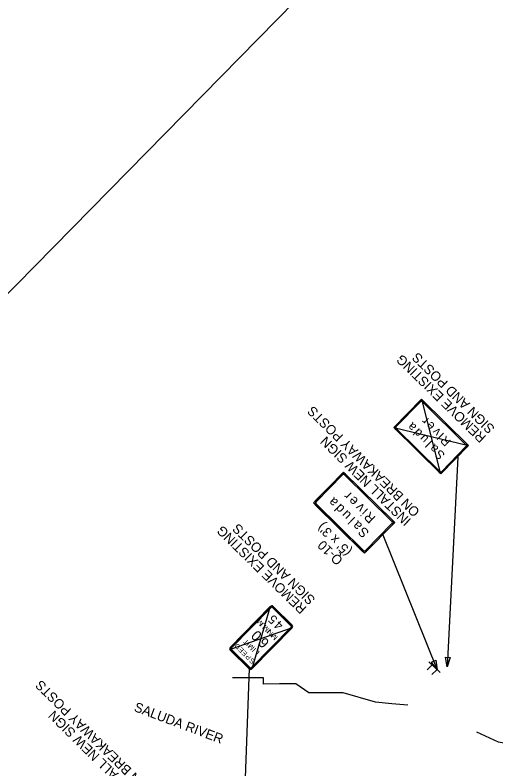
# Model space of a CAD drawing. Extents: x -5665 to 1997148, y 4 to 812485.
# Drawn here: x 1960138 to 1961396, y 797671 to 799640 of the extents above; entities that cross this region are included whole.
import ezdxf

# ---------------------------------------------------------------- set-up
doc = ezdxf.new("R2010")
doc.units = 0
for name, color, linetype in [('RD_EX_H20_TX', 7, 'Continuous'), ('RD_EX_Misc', 7, 'Continuous'), ('RD_PD_Final_TX', 7, 'Continuous'), ('RD_SHT_ID', 7, 'Continuous'), ('RD_SHT_TX', 7, 'Continuous')]:
    doc.layers.add(name, color=color, linetype=linetype)

msp = doc.modelspace()

# ---------------------------------------------------------------- linework, layer by layer
at = {"layer": 'RD_EX_H20_TX'}
msp.add_lwpolyline([(1962404, 800141.4), (1963753.3, 798814), (1964835.2, 797771.3), (1960364.2, 793199.8), (1958829.3, 794809.7), (1958381.6, 795250.1), (1957464.7, 796215.1), (1961650.1, 800469.8)], close=True, dxfattribs=at)
at = {"layer": 'RD_EX_Misc'}
for p, q in [((1961295.8, 798485.3), (1961268.2, 797937.9)), ((1960730.9, 797390.2), (1960751.5, 797933.4))]:
    msp.add_line(p, q, dxfattribs=at)
at = {"layer": 'RD_PD_Final_TX'}
for points in [[(1961226.9, 797950.3), (1961238.3, 797955.1), (1961242.2, 797929.8)], [(1961264.1, 797963.2), (1961276.5, 797962.2), (1961268.2, 797937.9)]]:
    msp.add_lwpolyline(points, close=True, dxfattribs=at)
at = {"layer": 'RD_SHT_ID'}
for points in [[(1961165.7, 797837.4), (1961123.4, 797841.3), (1961081.1, 797845.2), (1960996.3, 797869.9), (1960906.4, 797870.3), (1960872.3, 797893.3), (1960830, 797893), (1960787.7, 797892.6), (1960787.6, 797909.5), (1960735.8, 797909.1), (1960707.2, 797908.9)], [(1961345.1, 797768), (1961401.3, 797742), (1961401.3, 797742), (1961437.4, 797736), (1961492, 797726.8), (1961530.7, 797705)]]:
    msp.add_lwpolyline(points, dxfattribs=at)
at = {"layer": 'RD_SHT_TX'}
for p, q in [((1961201, 798636.6), (1961248.8, 798448.4)), ((1961128.5, 798562.8), (1961324, 798515.6)), ((1961099.8, 798282.4), (1961242.2, 797929.8)), ((1960805.8, 798095.6), (1960700.7, 797988.6)), ((1960805.8, 798095.6), (1960757.7, 797932.5)), ((1960862.8, 798046.5), (1960812.9, 798095.6)), ((1960862.9, 798039.5), (1960703.1, 797983.9)), ((1960757.7, 797932.5), (1960862.9, 798039.5)), ((1960700.7, 797981.6), (1960750.6, 797932.5)), ((1961249.6, 797922.7), (1961220, 797951.2)), ((1961216.2, 797930.1), (1961228.6, 797943)), ((1961228.4, 797917.4), (1961240.8, 797930.3))]:
    msp.add_line(p, q, dxfattribs=at)
for points in [[(1961324, 798515.6), (1961201, 798636.6), (1961128.5, 798562.8), (1961251.4, 798441.8), (1961324, 798515.6), (1961324, 798515.6), (1961324, 798515.6)], [(1961198.5, 798629.9), (1961135, 798565.4)], [(1961198.5, 798629.9), (1961198.5, 798629.9), (1961198.5, 798629.9)], [(1961317.4, 798518.1), (1961203.6, 798630)], [(1961135.1, 798560.3), (1961248.8, 798448.4)], [(1961135.1, 798560.3), (1961135.1, 798560.3), (1961135.1, 798560.3)], [(1961317.4, 798518.1), (1961317.4, 798518.1), (1961317.4, 798518.1)], [(1961253.9, 798448.4), (1961317.4, 798513)], [(1961131, 798314.8), (1960997.3, 798446.3), (1960918.4, 798366.1), (1961052.1, 798234.6), (1961131, 798314.8), (1961131, 798314.8), (1961131, 798314.8)], [(1960923.4, 798371.1), (1960992.4, 798441.3)], [(1960994.6, 798439.1), (1960925.6, 798368.9)], [(1960994.6, 798439.1), (1960994.6, 798439.1), (1960994.6, 798439.1)], [(1961123.8, 798317.5), (1961000.1, 798439.1)], [(1961002.3, 798441.3), (1961126, 798319.7)], [(1961253.9, 798448.4), (1961253.9, 798448.4), (1961253.9, 798448.4)], [(1961047.1, 798239.5), (1960923.4, 798361.1)], [(1960925.6, 798363.4), (1961049.3, 798241.7)], [(1960925.6, 798363.4), (1960925.6, 798363.4), (1960925.6, 798363.4)], [(1961054.8, 798241.8), (1961123.8, 798312)], [(1961126.1, 798309.8), (1961057, 798239.6)], [(1961123.8, 798317.5), (1961123.8, 798317.5), (1961123.8, 798317.5)], [(1961054.8, 798241.8), (1961054.8, 798241.8), (1961054.8, 798241.8)], [(1960806.7, 798094.7), (1960701.5, 797987.8)], [(1960703, 797986.3), (1960808.2, 798093.2)], [(1960806.7, 798094.7), (1960806.7, 798094.7), (1960806.7, 798094.7)], [(1960810.6, 798093.3), (1960860.5, 798044.2)], [(1960861.9, 798045.6), (1960812, 798094.7)], [(1960861.9, 798045.6), (1960861.9, 798045.6), (1960861.9, 798045.6)], [(1960860.5, 798041.8), (1960755.3, 797934.9)], [(1960756.8, 797933.4), (1960862, 798040.3)], [(1960701.6, 797982.5), (1960751.5, 797933.4)], [(1960701.6, 797982.5), (1960701.6, 797982.5), (1960701.6, 797982.5)], [(1960753, 797934.9), (1960703.1, 797983.9)], [(1960756.8, 797933.4), (1960756.8, 797933.4), (1960756.8, 797933.4)]]:
    msp.add_lwpolyline(points, dxfattribs=at)
for centre, radius, start, end in [((1961201.1, 798627.4), 6.47, 45.4705, 135.4707), ((1961201.1, 798627.4), 3.59, 45.4705, 135.4707), ((1961137.6, 798562.8), 6.47, 135.4705, 225.4707), ((1961137.6, 798562.8), 3.59, 135.4705, 225.4707), ((1961314.9, 798515.5), 3.59, 315.4703, 45.4705), ((1961314.9, 798515.5), 6.47, 315.4703, 45.4705), ((1960997.4, 798436.3), 7.03, 45.4705, 135.4707), ((1960997.4, 798436.3), 3.91, 45.4705, 135.4707), ((1961251.4, 798450.9), 6.47, 225.4707, 315.4703), ((1961251.4, 798450.9), 3.59, 225.4707, 315.4703), ((1960928.4, 798366.1), 7.03, 135.4705, 225.4707), ((1960928.4, 798366.1), 3.91, 135.4705, 225.4707), ((1961121.1, 798314.7), 3.91, 315.4703, 45.4705), ((1961121.1, 798314.7), 7.03, 315.4703, 45.4705), ((1961052, 798244.5), 3.91, 225.4707, 315.4703), ((1961052, 798244.5), 7.03, 225.4707, 315.4703), ((1960809.4, 798092.1), 5, 45.4705, 135.4707), ((1960809.4, 798092.1), 3.75, 45.4705, 135.4707), ((1960809.4, 798092.1), 1.67, 45.4705, 135.4707), ((1960859.3, 798043), 3.75, 315.4703, 45.4705), ((1960859.3, 798043), 5, 315.4703, 45.4705), ((1960859.3, 798043), 1.67, 315.4703, 45.4705), ((1960704.2, 797985.1), 5, 135.4705, 225.4707), ((1960704.2, 797985.1), 3.75, 135.4705, 225.4707), ((1960704.2, 797985.1), 1.67, 135.4705, 225.4707), ((1960754.1, 797936), 5, 225.4707, 315.4703), ((1960754.1, 797936), 3.75, 225.4707, 315.4703), ((1960754.1, 797936), 1.67, 225.4707, 315.4703)]:
    msp.add_arc(centre, radius, start, end, dxfattribs=at)

# ---------------------------------------------------------------- texts
for s, height, rotation, p in [('SIGN AND POSTS', 25, 135.6376, (1961394.5, 798562.2)), ('REMOVE EXISTING', 25, 135.6376, (1961371.7, 798539)), ('ON BREAKAWAY POSTS', 25, 135.4705, (1961198.4, 798344.8)), ('a', 23, 135.4705, (1961189.7, 798566)), ('r', 23, 135.4705, (1961222.1, 798584.6)), ('e', 23, 135.4705, (1961237.9, 798569)), ('d', 23, 135.4705, (1961205.4, 798550.6)), ('v', 23, 135.4705, (1961253.5, 798553.7)), ('INSTALL NEW SIGN', 25, 135.4705, (1961175.5, 798321.6)), ('u', 23, 135.4705, (1961221.1, 798535.2)), ('i', 23, 135.4705, (1961261.2, 798546.1)), ('R', 23, 135.4705, (1961279.8, 798527.8)), ('l', 23, 135.4705, (1961230.5, 798525.9)), ('a', 23, 135.4705, (1961247.3, 798509.3)), ('S', 23, 135.4705, (1961264.2, 798492.7)), ('a', 25, 135.4705, (1960985, 798369.6)), ('r', 25, 135.4705, (1961020.2, 798389.8)), ('e', 25, 135.4705, (1961037.4, 798372.9)), ('d', 25, 135.4705, (1961002.1, 798352.8)), ('v', 25, 135.4705, (1961054.4, 798356.2)), ('u', 25, 135.4705, (1961019.1, 798336)), ('i', 25, 135.4705, (1961062.7, 798347.9)), ('R', 25, 135.4705, (1961082.9, 798328.1)), ('l', 25, 135.4705, (1961029.4, 798326)), ('a', 25, 135.4705, (1961047.7, 798308)), ('REMOVE EXISTING', 25, 135.6376, (1960902.3, 798091.9)), ('SIGN AND POSTS', 25, 135.6376, (1960925, 798115.2)), ("(5' x 3')", 25, 135.6376, (1961020.3, 798241.6)), ('S', 25, 135.4705, (1961066, 798289.9)), ('Q-10', 25, 135.6376, (1960997.5, 798218.4)), ('5', 23.3, 135.4705, (1960826.4, 798063.6)), ('M', 13.3, 135.4705, (1960788.9, 798052.6)), ('U', 13.3, 135.4705, (1960796.1, 798045.5)), ('M', 13.3, 135.4705, (1960804.3, 798037.5)), ('4', 23.3, 135.4705, (1960841.8, 798048.5)), ('0', 26.7, 135.4705, (1960785.9, 798021.6)), ('I', 13.3, 135.4705, (1960807.6, 798034.2)), ('N', 13.3, 135.4705, (1960814.8, 798027.1)), ('I', 13.3, 135.4705, (1960818.2, 798023.8)), ('M', 13.3, 135.4705, (1960826.3, 798015.8)), ('T', 13.3, 135.4705, (1960750.9, 798003.5)), ('6', 26.7, 135.4705, (1960805, 798002.9)), ('D', 13.3, 135.4705, (1960729.1, 797991.1)), ('E', 13.3, 135.4705, (1960738.1, 797982.2)), ('I', 13.3, 135.4705, (1960754.5, 798000)), ('M', 13.3, 135.4705, (1960765.7, 797988.9)), ('I', 13.3, 135.4705, (1960769.8, 797984.9)), ('E', 13.3, 135.4705, (1960747.1, 797973.4)), ('P', 13.3, 135.4705, (1960757.2, 797963.5)), ('L', 13.3, 135.4705, (1960778.7, 797976.1)), ('S', 13.3, 135.4705, (1960767.2, 797953.5)), ('ON BREAKAWAY POSTS', 25, 135.4705, (1960487.1, 797628.9)), ('SALUDA RIVER', 25, 339.371, (1960447.4, 797822.9)), ('INSTALL NEW SIGN', 25, 135.4705, (1960464.3, 797605.7))]:
    msp.add_text(s, height=height, rotation=rotation, dxfattribs=at).set_placement(p)

doc.saveas('drawing.dxf')
